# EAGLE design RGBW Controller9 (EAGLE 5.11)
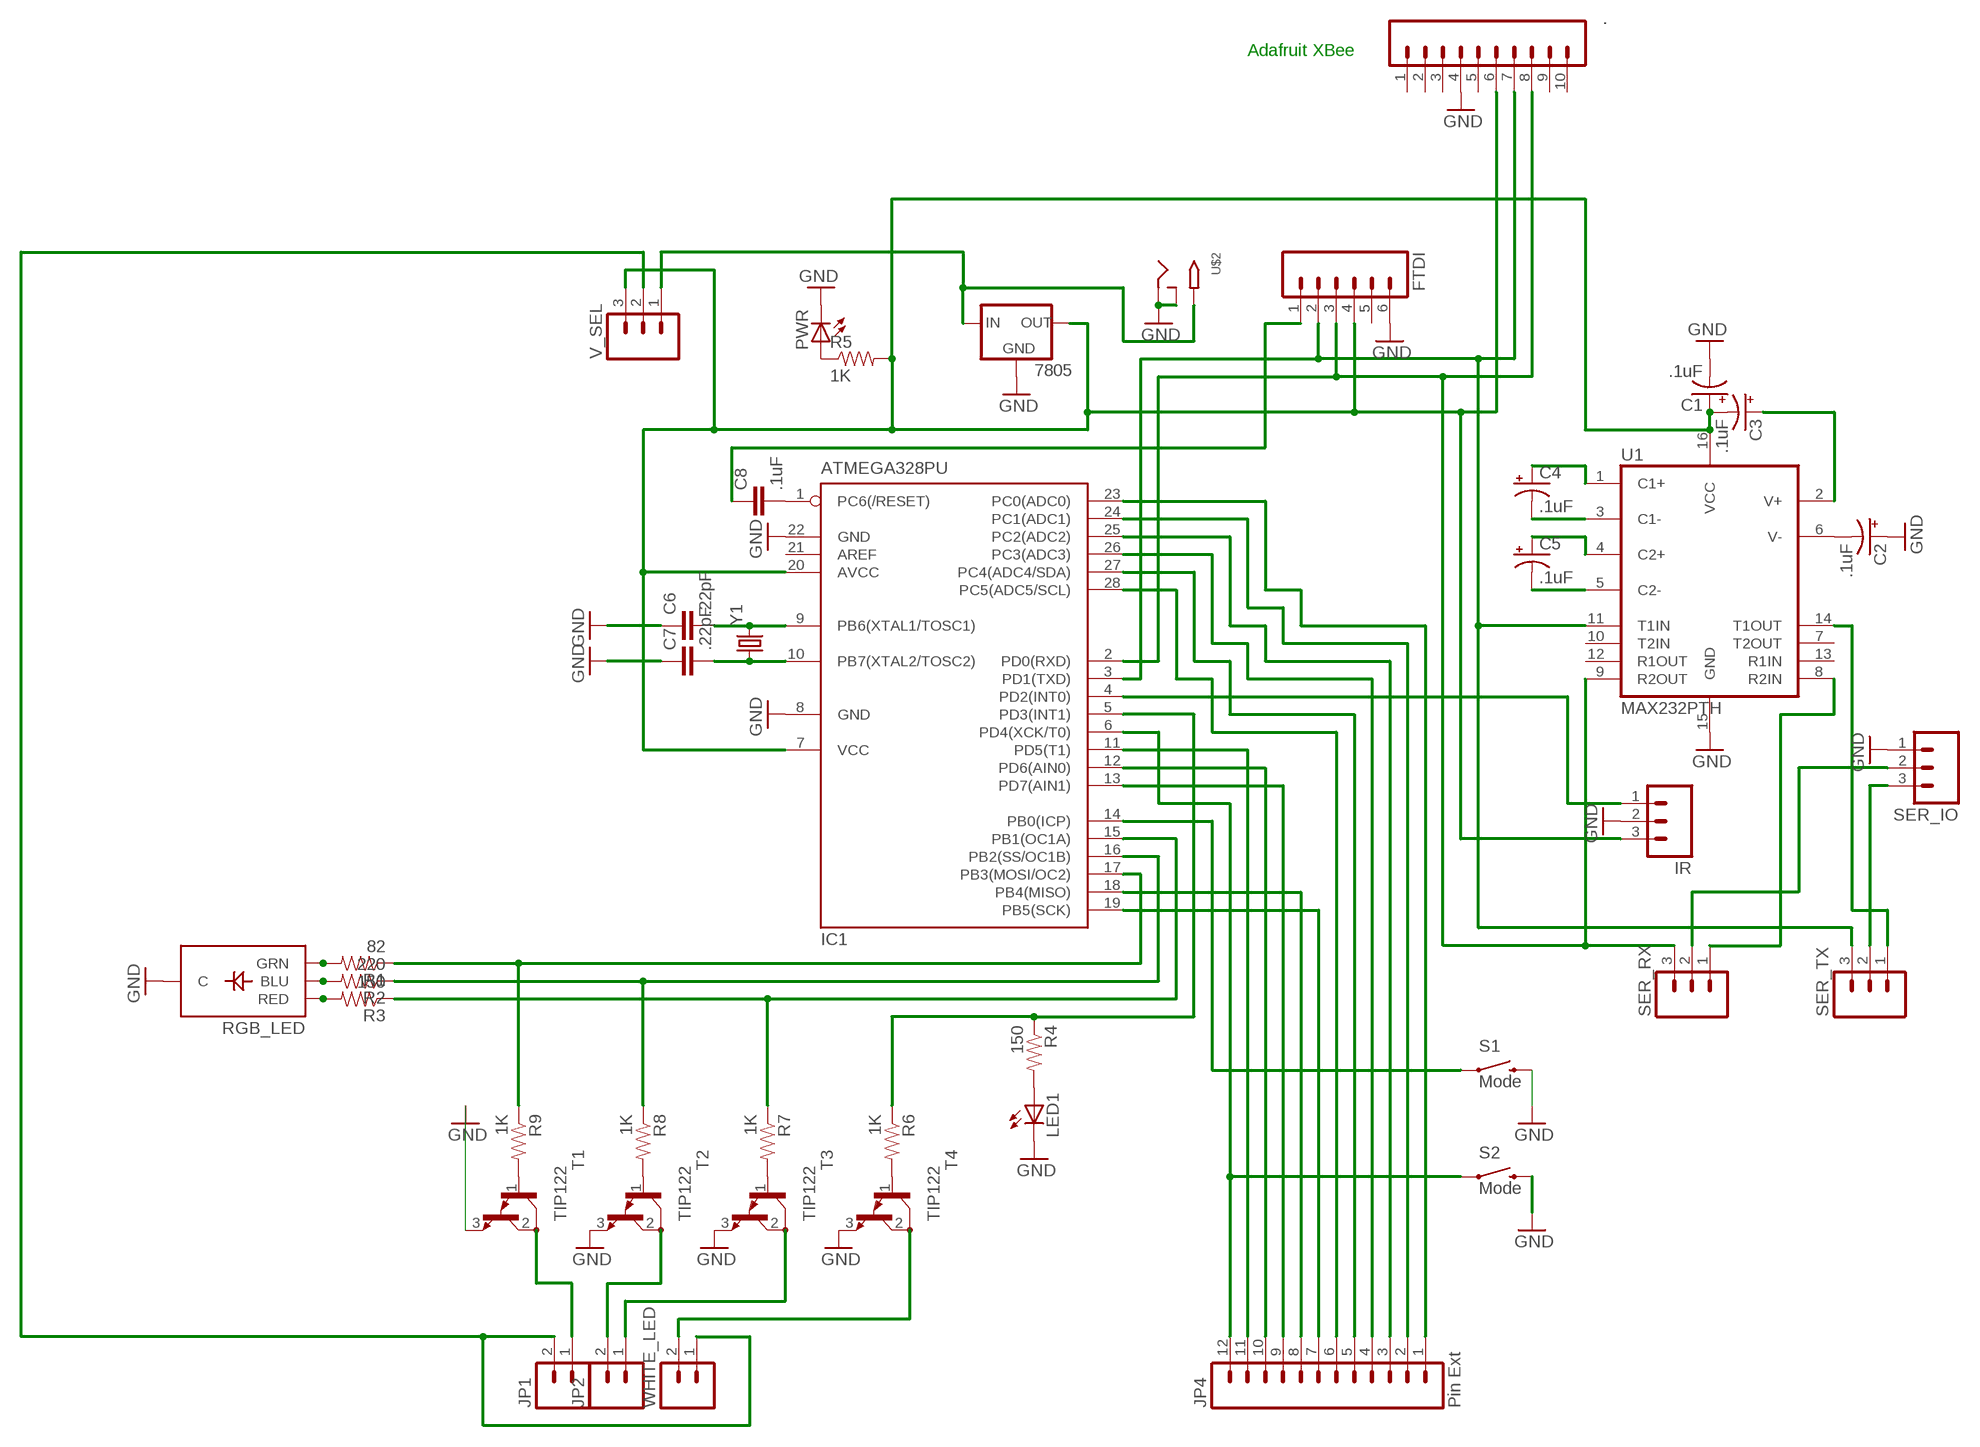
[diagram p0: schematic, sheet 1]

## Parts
7805  V_REG_78XXSIDE  [78XXL]
.  M10"  [1X10]
C1  .1uF  CAP_POLPTH1  [CPOL-RADIAL-100UF-25V]
C2  .1uF  CAP_POLPTH1  [CPOL-RADIAL-100UF-25V]
C3  .1uF  CAP_POLPTH1  [CPOL-RADIAL-100UF-25V]
C4  .1uF  CAP_POLPTH1  [CPOL-RADIAL-100UF-25V]
C5  .1uF  CAP_POLPTH1  [CPOL-RADIAL-100UF-25V]
C6  .22pF  CAPPTH  [CAP-PTH-SMALL]
C7  .22pF  CAPPTH  [CAP-PTH-SMALL]
C8  .1uF  CAPKIT  [CAP-PTH-SMALL-KIT]
FTDI  M06SIP  [1X06]
IC1  ATMEGA328PU  MEGA8-P  [DIL28-3]
IR  M03PTH  [1X03]
JP1  M023.5MM_LOCK  [SCREWTERMINAL-3.5MM-2_LOCK]
JP2  M023.5MM_LOCK  [SCREWTERMINAL-3.5MM-2_LOCK]
JP4  Pin Ext  M12LONGPADS  [1X12_LONGPADS]
LED1  LED5MM  [LED5MM]
PWR  LED5MM  [LED5MM]
R1  82  RESISTORPTH-1/4W  [AXIAL-0.4]
R2  220  RESISTORPTH-1/4W  [AXIAL-0.4]
R3  150  RESISTORPTH-1/4W  [AXIAL-0.4]
R4  150  RESISTORPTH-1/4W  [AXIAL-0.4]
R5  1K  RESISTORPTH-1/4W  [AXIAL-0.4]
R6  1K  RESISTORPTH-1/4W  [AXIAL-0.4]
R7  1K  RESISTORPTH-1/4W  [AXIAL-0.4]
R8  1K  RESISTORPTH-1/4W  [AXIAL-0.4]
R9  1K  RESISTORPTH-1/4W  [AXIAL-0.4]
RGB_LED  LED-TRICOLOR-THROUGHHOLE  [LED-TRICOLOR-THROUGHHOLE]
S1  Mode  SWITCH-MOMENTARY-2PTH  [TACTILE-PTH]
S2  Mode  SWITCH-MOMENTARY-2PTH  [TACTILE-PTH]
SER_IO  M03-SCREW-5MM  [SCREWTERMINAL-5MM-3]
SER_RX  M03PTH  [1X03]
SER_TX  M03PTH  [1X03]
T1  TIP122  [TO220]
T2  TIP122  [TO220]
T3  TIP122  [TO220]
T4  TIP122  [TO220]
U1  MAX232PTH  [DIL16]
U$2  2.1MMJACKTHM  [PJ-102A]
V_SEL  M03PTH  [1X03]
WHITE_LED  M023.5MM_LOCK  [SCREWTERMINAL-3.5MM-2_LOCK]
Y1  CRYSTALHC49US  [HC49US]

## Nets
GND: 7805.GND ..4 C1.2(-) C2.1(+) C6.1 C7.1 FTDI.6 IC1.8(GND) IC1.22(GND) IR.2 LED1.K(C) PWR.K(C) RGB_LED.GND(C) S1.3 S2.3 SER_IO.1 T1.3(E) T2.3(E) T3.3(E) T4.3(E) U1.15(GND) U$2.RING U$2.RING_SW
N$1: R1.P$2 RGB_LED.GRN
N$2: R2.P$2 RGB_LED.BLU
N$3: R3.P$2 RGB_LED.RED
N$4: LED1.A R4.P$2
N$5: PWR.A R5.P$1
N$6: C5.1(+) U1.4(C2+)
N$7: C4.2(-) U1.3(C1-)
N$8: C4.1(+) U1.1(C1+)
N$9: C5.2(-) U1.5(C2-)
N$10: IC1.19(PB5(SCK)) JP4.7
N$11: C3.1(+) U1.2(V+)
N$12: C2.2(-) U1.6(V-)
N$13: IC1.5(PD3(INT1)) R4.P$1 R6.P$1
N$14: IC1.15(PB1(OC1A)) R3.P$1 R7.P$1
N$15: IC1.16(PB2(SS/OC1B)) R2.P$1 R8.P$1
N$16: IC1.17(PB3(MOSI/OC2)) R1.P$1 R9.P$1
N$17: C6.2 IC1.9(PB6(XTAL1/TOSC1)) Y1.2
N$18: C7.2 IC1.10(PB7(XTAL2/TOSC2)) Y1.1
N$19: IC1.4(PD2(INT0)) IR.1
N$20: JP1.2 V_SEL.2 WHITE_LED.1
N$21: JP1.1 T1.2(C)
N$22: 7805.OUT ..6 C1.1(+) C3.2(-) FTDI.4 IC1.7(VCC) IC1.20(AVCC) IR.3 R5.P$2 U1.16(VCC) V_SEL.3
N$23: JP2.2 T2.2(C)
N$24: JP2.1 T3.2(C)
N$25: T4.2(C) WHITE_LED.2
N$26: IC1.14(PB0(ICP)) S1.1
N$27: C8.2 IC1.1(PC6(/RESET))
N$28: C8.1 FTDI.1
N$29: ..7 FTDI.2 IC1.3(PD1(TXD)) SER_TX.3 U1.11(T1IN)
N$30: ..8 FTDI.3 IC1.2(PD0(RXD)) SER_RX.3 U1.9(R2OUT)
N$31: IC1.18(PB4(MISO)) JP4.8
N$32: IC1.13(PD7(AIN1)) JP4.9
N$33: IC1.12(PD6(AIN0)) JP4.10
N$34: IC1.11(PD5(T1)) JP4.11
N$35: IC1.26(PC3(ADC3)) JP4.4
N$36: IC1.27(PC4(ADC4/SDA)) JP4.5
N$37: IC1.28(PC5(ADC5/SCL)) JP4.6
N$38: IC1.6(PD4(XCK/T0)) JP4.12 S2.1
N$39: IC1.25(PC2(ADC2)) JP4.3
N$40: IC1.24(PC1(ADC1)) JP4.2
N$41: IC1.23(PC0(ADC0)) JP4.1
N$42: SER_IO.3 SER_TX.2
N$43: SER_IO.2 SER_RX.2
N$44: SER_TX.1 U1.14(T1OUT)
N$45: SER_RX.1 U1.8(R2IN)
N$46: R7.P$2 T3.1(B)
N$47: R8.P$2 T2.1(B)
N$48: R9.P$2 T1.1(B)
N$49: R6.P$2 T4.1(B)
N$50: 7805.IN U$2.TIP V_SEL.1
Unconnected: ..1 ..2 ..3 ..5 ..9 ..10 FTDI.5 IC1.21(AREF) U1.7(T2OUT) U1.10(T2IN) U1.12(R1OUT) U1.13(R1IN)

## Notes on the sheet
- Adafruit XBee

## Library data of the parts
7805 = SparkFun:V_REG_78XX: Voltage Regulator Standard 7805 5V regulator. IGO (Input Ground Output). Spark Fun Electronics SKU : COM-00107
. = SparkFun:M10: Header 10 Standard 10-pin 0.1" header. Use with straight break away headers (SKU : PRT-00116), right angle break away headers (PRT-00553), swiss pins (PRT-00743), machine pins (PRT-00117), and female headers (PRT-00115).
C1-C5 = SparkFun:CAP_POL: Capacitor Polarized
C6-C8 = SparkFun:CAP: Capacitor
FTDI = SparkFun:M06: Header 6 Standard 6-pin 0.1" header. Use with straight break away headers (SKU : PRT-00116), right angle break away headers (PRT-00553), swiss pins (PRT-00743), machine pins (PRT-00117), and female headers (PRT-00115). Molex polarized connector foot print use with SKU : PRT-08094 with associated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
IC1 = atmel:MEGA8-P: MICROCONTROLLER 8 Kbytes FLASH, 1 kbytes SRAM, 512 bytes EEPROM, USART, 4-channel 10 bit ADC, 2-channel 8 bit ADC Pin compatible with Atmega48, ATMega88, ATMega168 Source: avr.lbr
IR SER_IO SER_RX SER_TX V_SEL = SparkFun:M03: Header 3 Standard 3-pin 0.1" header. Use with straight break away headers (SKU : PRT-00116), right angle break away headers (PRT-00553), swiss pins (PRT-00743), machine pins (PRT-00117), and female headers (PRT-00115). Molex polarized connector foot print use with SKU : PRT-08232 with associated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
JP1 JP2 WHITE_LED = SparkFun:M02: Header 2
JP4 = SparkFun:M12: Header 12 Standard 12-pin 0.1" header. Use with straight break away headers (SKU : PRT-00116), right angle break away headers (PRT-00553), swiss pins (PRT-00743), machine pins (PRT-00117), and female headers (PRT-00115).
LED1 PWR = led:LED: LED
R1-R9 = SparkFun:RESISTOR: Resistor
RGB_LED = SparkFun:LED-TRICOLOR-THROUGHHOLE
S1 S2 = SparkFun:SWITCH-MOMENTARY-2
T1-T4 = transistor:TIP122: NPN BIPOLAR DARLINGTON TRANSISTOR
U1 = SparkFun:MAX232: RS232 Transceiver Very common IC. This is generically called 'MAX232', but works with the 3V equivalent MAX3232 generic ICs. Field tested and mother approved. Spark Fun Electronics SKU : COM-00316 (DIP) and COM-00589 (SMD)
U$2 = adafruit:2.1MMJACK: 2.1mm x 5.5mm THM DC jack with internal switch. Digikey part #PJ-102A, 4UCON part #05537 2.1mm x 5.5mm SMT DC jack with internal switch. Digikey part #PJ-002A-SMT, 4UCON part #03267 By microbuilder.eu & adafruit.com
Y1 = SparkFun:CRYSTAL: Crystals

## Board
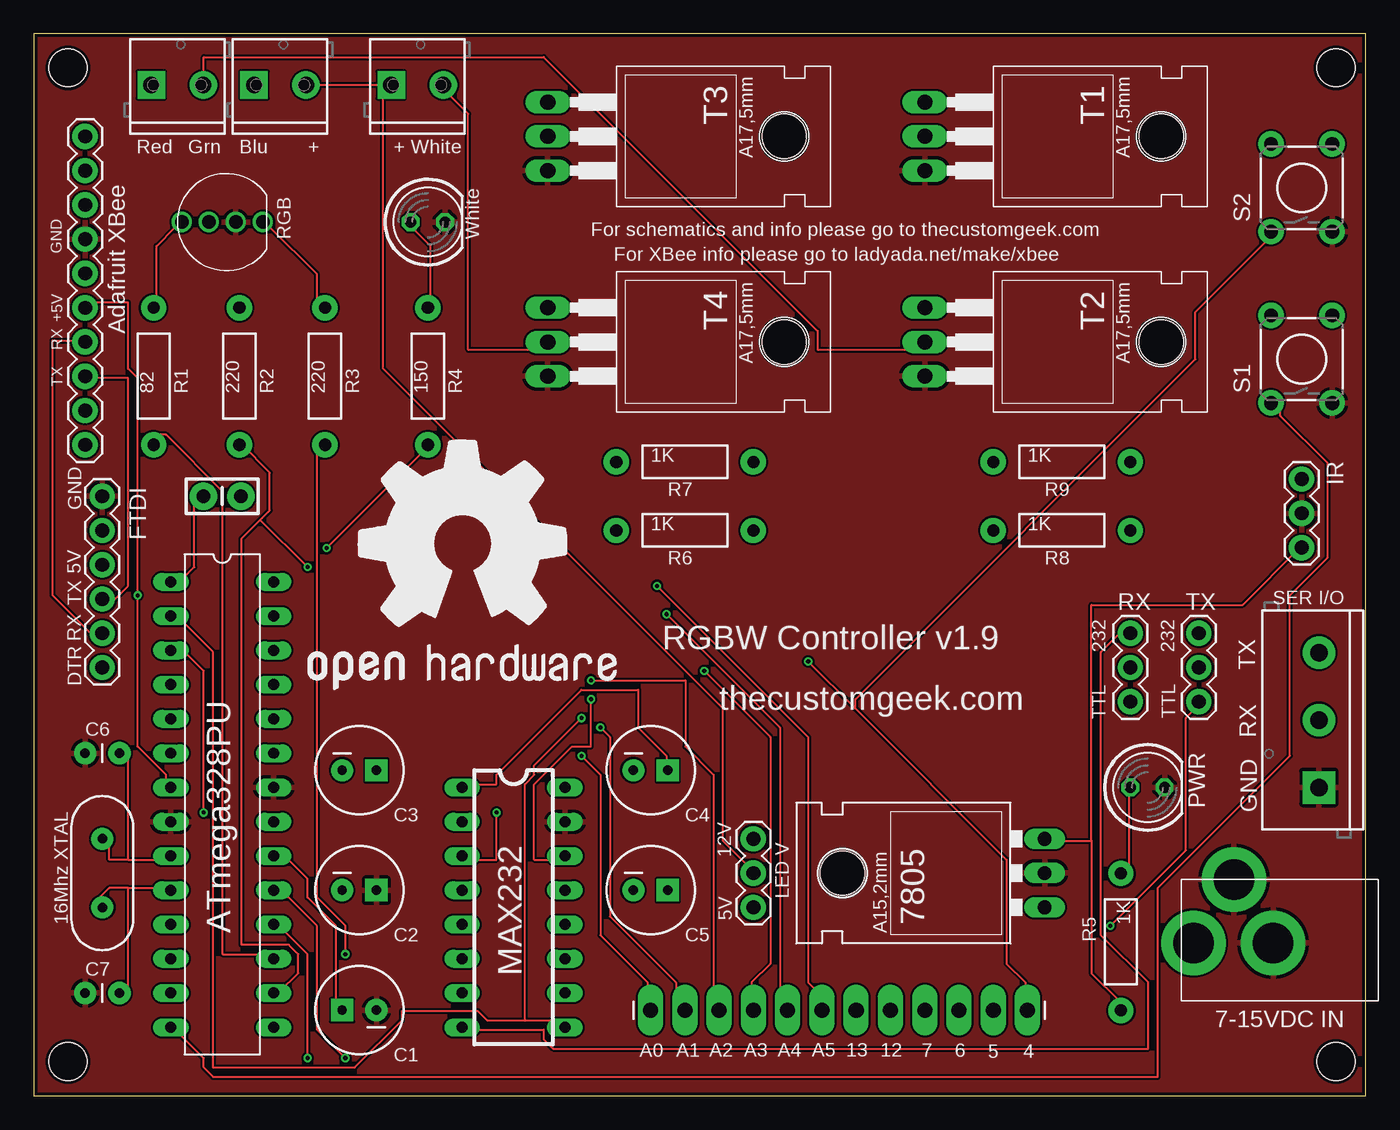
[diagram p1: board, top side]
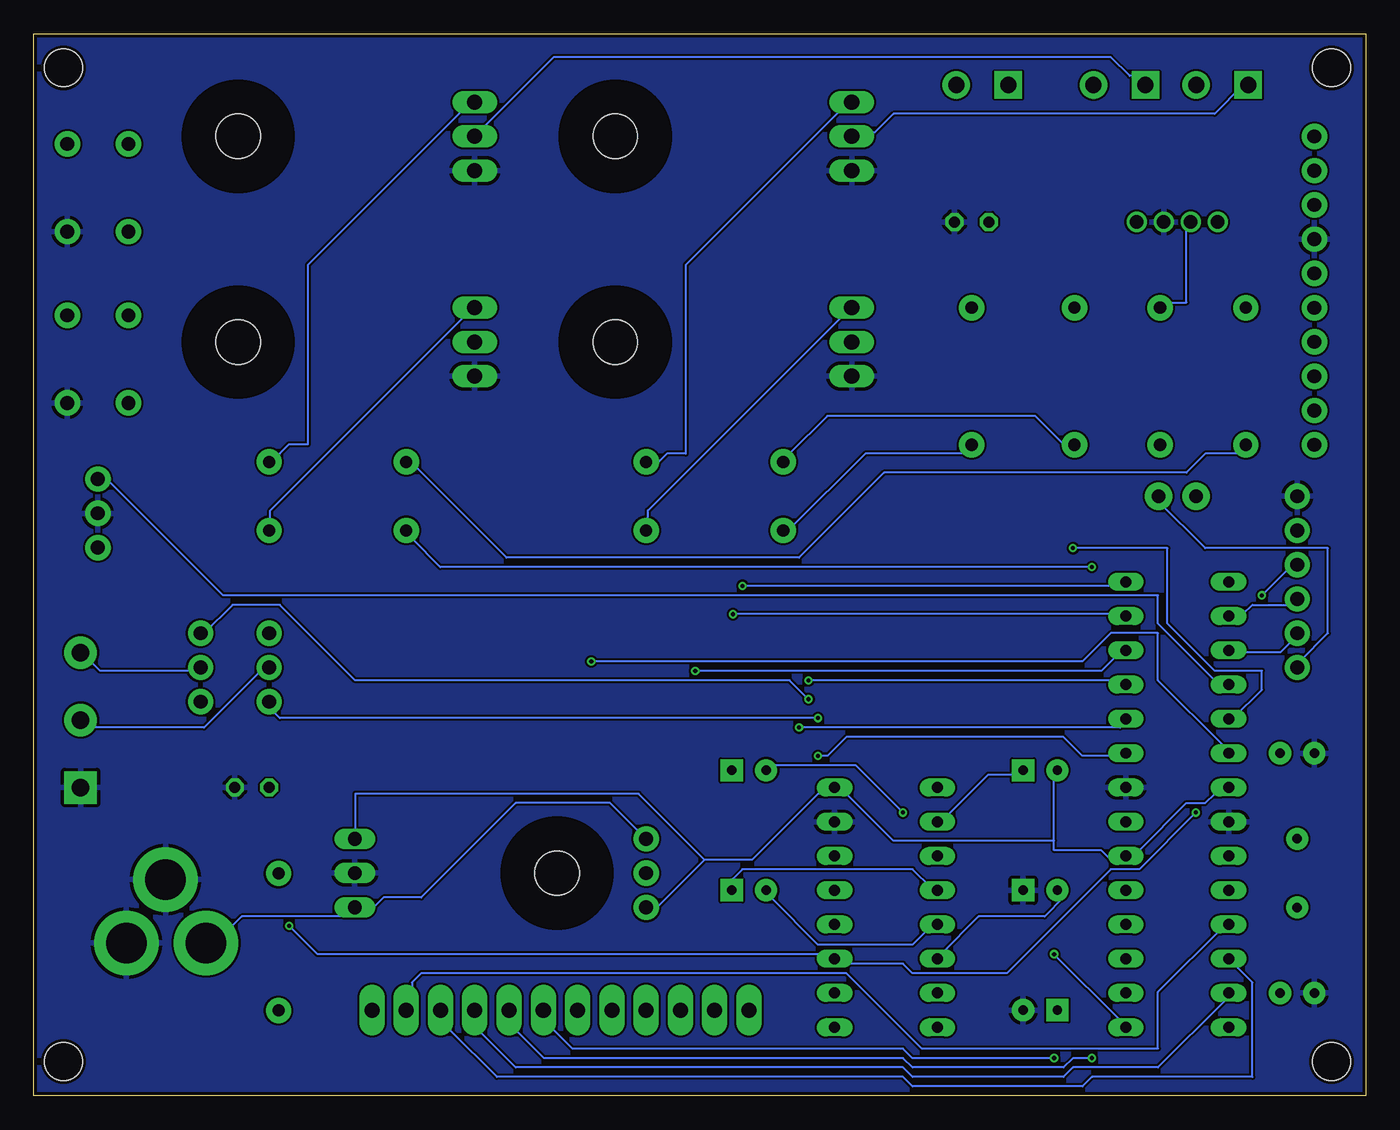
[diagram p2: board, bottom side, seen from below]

Size 98.73 x 78.73 mm. Coordinates in mm from the lower left corner, seen from the top.
Outline: 0,0 98.73,0 98.73,78.73 0,78.73 0,0
Copper layers (1*16): Top 0.035mm / dielectric 1.5mm / Bottom 0.035mm
Design rules "Fusion_eagle_rule_v1.1": minimum track width 6mil, minimum drill 12mil, track to track 6mil, track to pad 6mil, pad to pad 6mil, via to via 6mil, smd to smd 0mil, copper to edge 10mil, drill to drill 10mil, minimum pad ring 10mil, minimum via ring 6mil, stop-mask expansion 2mil, vias tented up to drill 100mil, thermal gap 10mil
Holes 2.8 mm at 2.54,76.2 2.54,2.54 96.52,2.54 96.52,76.2

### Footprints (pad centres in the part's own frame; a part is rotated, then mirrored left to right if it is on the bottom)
78XXL = drill 1.016 long: GND 0,-3.81; IN -2.54,-3.81; OUT 2.54,-3.81 | hole 3.302: 0,11.176
1X10 = drill 1.016 pad 1.88 round: 1 0,0; 2 2.54,0; 3 5.08,0; 4 7.62,0; 5 10.16,0; 6 12.7,0; 7 15.24,0; 8 17.78,0; 9 20.32,0; 10 22.86,0
CPOL-RADIAL-100UF-25V = drill 0.7 pad 1.651 square: 1 1.27,0 | drill 0.7 pad 1.651 round: 2 -1.27,0
CAP-PTH-SMALL = drill 0.7 pad 1.651 round: 1 0,0; 2 2.54,0
CAP-PTH-SMALL-KIT = drill 1.016 pad 2.032 round: 1 -1.397,0; 2 1.397,0
1X06 = drill 1.016 pad 1.88 round: 1 0,0; 2 2.54,0; 3 5.08,0; 4 7.62,0; 5 10.16,0; 6 12.7,0
DIL28-3 = drill 0.813 long: 1 -16.51,-3.81; 2 -13.97,-3.81; 3 -11.43,-3.81; 4 -8.89,-3.81; 5 -6.35,-3.81; 6 -3.81,-3.81; 7 -1.27,-3.81; 8 1.27,-3.81; 9 3.81,-3.81; 10 6.35,-3.81; 11 8.89,-3.81; 12 11.43,-3.81; 13 13.97,-3.81; 14 16.51,-3.81; 15 16.51,3.81; 16 13.97,3.81; 17 11.43,3.81; 18 8.89,3.81; 19 6.35,3.81; 20 3.81,3.81; 21 1.27,3.81; 22 -1.27,3.81; 23 -3.81,3.81; 24 -6.35,3.81; 25 -8.89,3.81; 26 -11.43,3.81; 27 -13.97,3.81; 28 -16.51,3.81
1X03 = drill 1.016 pad 1.88 round: 1 0,0; 2 2.54,0; 3 5.08,0
SCREWTERMINAL-3.5MM-2_LOCK = drill 1.2 pad 2.032 square: 1 -0.178,0 | drill 1.2 pad 2.032 round: 2 3.678,0
1X12_LONGPADS = drill 1.118 pad 1.88 long: 1 0,0; 2 2.54,0; 3 5.08,0; 4 7.62,0; 5 10.16,0; 6 12.7,0; 7 15.24,0; 8 17.78,0; 9 20.32,0; 10 22.86,0; 11 25.4,0; 12 27.94,0
LED5MM = drill 0.813 octagon: A -1.27,0; K 1.27,0
AXIAL-0.4 = drill 0.9 pad 1.88 round: P$1 -5.08,0; P$2 5.08,0
LED-TRICOLOR-THROUGHHOLE = drill 1 round: BLU 1,0; GND -1,0; GRN 3,0; RED -3,0
TACTILE-PTH = drill 1.016 pad 1.88 round: 1 -3.251,2.261; 2 3.251,2.261; 3 -3.251,-2.261; 4 3.251,-2.261
SCREWTERMINAL-5MM-3 = drill 1.3 pad 2.413 square: 1 0,0 | drill 1.3 pad 2.413 round: 2 5,0; 3 10,0
TO220 = drill 1.118 long: 1 -2.54,-6.35; 2 0,-6.35; 3 2.54,-6.35 | hole 3.302: 0,11.176
DIL16 = drill 0.813 long: 1 -8.89,-3.81; 2 -6.35,-3.81; 3 -3.81,-3.81; 4 -1.27,-3.81; 5 1.27,-3.81; 6 3.81,-3.81; 7 6.35,-3.81; 8 8.89,-3.81; 9 8.89,3.81; 10 6.35,3.81; 11 3.81,3.81; 12 1.27,3.81; 13 -1.27,3.81; 14 -3.81,3.81; 15 -6.35,3.81; 16 -8.89,3.81
PJ-102A = drill 3 pad 4.8 round: RING 0.1,-3.39; RING_SW -4.6,-6.29; TIP 0.1,-9.29
HC49US = drill 0.7 pad 1.651 round: 1 -2.54,0; 2 2.54,0

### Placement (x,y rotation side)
7805  71.12,16.51 90 top
.  3.81,71.12 270 top
C1  24.13,6.35 180 top
C2  24.13,15.24 0 top
C3  24.13,24.13 0 top
C4  45.72,24.13 0 top
C5  45.72,15.24 0 top
C6  3.81,25.4 0 top
C7  3.81,7.62 0 top
C8  13.97,44.45 180 top
FTDI  5.08,31.75 90 top
IC1  13.97,21.59 270 top
IR  93.98,45.72 270 top
JP1  16.51,74.93 0 top
JP2  8.89,74.93 0 top
JP4  45.72,6.35 0 top
LED1  29.21,64.77 0 top
PWR  82.55,22.86 0 top
R1  8.89,53.34 90 top
R2  15.24,53.34 90 top
R3  21.59,53.34 90 top
R4  29.21,53.34 90 top
R5  80.58,11.41 270 top
R6  48.26,41.91 0 top
R7  48.26,46.99 0 top
R8  76.2,41.91 0 top
R9  76.2,46.99 0 top
RGB_LED  13.97,64.77 180 top
S1  93.98,54.61 90 top
S2  93.98,67.31 90 top
SER_IO  95.25,22.86 90 top
SER_RX  81.28,34.29 270 top
SER_TX  86.36,34.29 270 top
T1  72.39,71.12 270 top
T2  72.39,55.88 270 top
T3  44.45,71.12 270 top
T4  44.45,55.88 270 top
U1  35.56,13.97 270 top
U$1  [OSHW0]  19.05,26.67 0 top
U$2  95.25,11.43 270 top
V_SEL  53.34,19.05 270 top
WHITE_LED  26.67,74.93 0 top
Y1  5.08,16.51 90 top

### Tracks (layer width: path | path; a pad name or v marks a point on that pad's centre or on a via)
GND
  pour Bottom: 0,78.74 99.06,78.74 99.06,0 0,0
  pour Top: 0,78.74 99.06,78.74 99.06,0 0,0
N$1
  Top 0.152: RGB_LED.GRN 10.5,64.4 9.1,63 9.1,58.8 R1.P$2
N$2
  Bottom 0.152: RGB_LED.BLU 13.3,64.4 13.3,58.8 14.7,58.8 R2.P$2
N$3
  Top 0.152: RGB_LED.RED 17.5,64.4 21,60.9 21,58.8 R3.P$2
N$4
  Top 0.152: LED1.A 28,64.4 29.4,63 29.4,58.8 R4.P$2
N$5
  Top 0.152: PWR.A 81.2,22.4 81.2,16.8 R5.P$1
N$6
  Bottom 0.152: U1.4 32.2,15.4 33.6,16.8 46.2,16.8 47.6,15.4 C5.1
N$7  (via drill 0.3)
  Top 0.152: v34.3,21 34.3,17.5 32.2,17.5 U1.3
  Bottom 0.152: v34.3,21 37.8,24.5 44.1,24.5 C4.2
N$8
  Top 0.152: U1.1 32.2,23.1 34.3,23.1 34.3,23.8 40.6,30.1 44.8,30.1 44.8,27.3 46.9,25.2 46.9,24.5 C4.1
N$9
  Bottom 0.152: U1.5 32.2,12.6 33.6,11.2 40.6,11.2 44.1,14.7 C5.2
N$10  (via drill 0.3)
  Top 0.152: v23.1,2.8 21,4.9 21,12.6 18.9,14.7 18.2,14.7 IC1.19
  Bottom 0.152: v23.1,2.8 33.6,2.8 34.3,3.5 58.8,3.5 61.6,6.3 JP4.7
N$11
  Bottom 0.152: U1.2 31.5,20.3 28,23.8 25.9,23.8 C3.1
N$12
  Bottom 0.152: U1.6 31.5,10.5 28.7,13.3 23.8,13.3 22.4,14.7 C2.2
N$13  (via drill 0.3)
  Top 0.152: v21.7,40.6 28.7,47.6 R4.P$1
  Bottom 0.152: v21.7,40.6 14.7,40.6 14.7,35 11.2,31.5 7.7,31.5 7.7,30.1 9.8,28 IC1.5 | R6.P$1 42.7,42 37.1,47.6 29.4,47.6 R4.P$1
N$14  (via drill 0.3)
  Top 0.152: v23.1,10.5 23.1,12.6 21,14.7 21,47.6 R3.P$1
  Bottom 0.152: v23.1,10.5 18.2,5.6 IC1.15 | R7.P$1 42.7,47.6 39.9,50.4 24.5,50.4 22.4,48.3 21.7,48.3 R3.P$1
N$15  (via drill 0.3)
  Top 0.152: 16.8,42.7 17.5,43.4 17.5,46.2 15.4,48.3 R2.P$1 | 16.8,42.7 15.4,41.3 15.4,11.2 18.9,11.2 19.6,10.5 19.6,9.1 18.2,7.7 IC1.16 | 16.8,42.7 v20.3,39.2
  Bottom 0.152: v20.3,39.2 68.6,39.2 70.7,41.3 R8.P$1
N$16
  Top 0.152: IC1.17 17.5,10.5 14,10.5 14,44.8 9.8,49 9.1,49 9.1,48.3 R1.P$1
  Bottom 0.152: R9.P$1 70.7,46.9 63.7,39.9 42,39.9 35.7,46.2 13.3,46.2 11.9,47.6 9.1,47.6 R1.P$1
N$17
  Top 0.152: 7,17.5 5.6,17.5 5.6,18.9 Y1.2 | 7,17.5 9.8,17.5 IC1.9 | 7,17.5 7,25.2 C6.2
N$18
  Top 0.152: 7,15.4 5.6,15.4 4.9,14.7 4.9,14 Y1.1 | 7,15.4 9.8,15.4 IC1.10 | 7,15.4 7,7.7 C7.2
N$19
  Bottom 0.152: IC1.4 10.5,30.8 11.2,30.8 15.4,35 15.4,37.1 84.7,37.1 93.1,45.5 93.8,45.5 IR.1
N$20
  Top 0.152: 25.9,74.9 25.9,53.9 51.1,28.7 51.1,18.9 53.2,16.8 V_SEL.2 | 25.9,74.9 20.3,74.9 JP1.2 | 25.9,74.9 WHITE_LED.1
N$21
  Bottom 0.152: T1.2 65.8,71.4 60.2,77 18.9,77 17.5,75.6 16.8,75.6 JP1.1
N$22  (via drill 0.3)
  Top 0.152: 78.4,18.9 75.6,18.9 7805.OUT | 78.4,18.9 78.4,9.1 80.5,7 R5.P$2 | 78.4,18.9 78.4,36.4 89.6,36.4 93.8,40.6 IR.3 | C1.1 22.4,7 22.4,12.6 20.3,14.7 20.3,16.1 18.2,18.2 IC1.20 | IC1.7 9.8,23.1 9.8,23.8 7.7,25.9 v7.7,37.1 7.7,53.2 7,53.9 7,58.8 4.2,58.8 ..6
  Bottom 0.152: 49,17.5 45.5,17.5 40.6,22.4 39.9,22.4 U1.16 39.2,22.4 38.5,22.4 35,18.9 23.1,18.9 | 49,17.5 52.5,14 53.2,14 V_SEL.3 | IC1.7 10.5,22.4 11.2,22.4 11.9,21.7 13.3,21.7 16.8,18.2 17.5,18.2 IC1.20 18.2,17.5 18.9,17.5 19.6,18.2 23.1,18.2 23.1,18.9 | 23.1,18.9 23.1,23.8 C3.2 | v7.7,37.1 5.6,39.2 FTDI.4 | 49,17.5 53.9,22.4 74.9,22.4 74.9,19.6 7805.OUT
N$23
  Top 0.152: T2.2 65.8,55.3 58.1,55.3 58.1,56.7 37.8,77 12.6,77 12.6,75.6 JP2.2
N$24
  Bottom 0.152: T3.2 37.8,71.4 36.4,71.4 35,72.8 11.2,72.8 9.1,74.9 JP2.1
N$25
  Top 0.152: T4.2 37.8,55.3 32.2,55.3 32.2,72.8 30.8,74.2 30.8,74.9 WHITE_LED.2
N$26
  Top 0.152: IC1.14 10.5,4.9 12.6,2.8 12.6,2.1 13.3,1.4 83.3,1.4 83.3,15.4 93.1,25.2 93.1,37.1 95.9,39.9 95.9,46.9 92.4,50.4 92.4,51.1 S1.1
N$27
  Top 0.152: IC1.1 10.5,38.5 11.2,38.5 11.9,39.2 11.9,44.1 C8.2
N$28
  Bottom 0.152: FTDI.1 4.9,32.2 2.8,34.3 2.8,40.6 11.9,40.6 15.4,44.1 C8.1
N$29  (via drill 0.3)
  Top 0.152: v12.6,21 12.6,31.5 10.5,33.6 IC1.3 | ..7 3.5,56 1.4,56 1.4,37.1 4.9,33.6 FTDI.2 | v79.8,12.6 85.4,18.2 85.4,28 86.1,28.7 SER_TX.3
  Bottom 0.152: IC1.3 9.8,32.9 6.3,32.9 5.6,33.6 FTDI.2 | v12.6,21 16.8,16.8 18.9,16.8 26.6,9.1 33.6,9.1 34.3,9.8 39.2,9.8 U1.11 39.9,10.5 77.7,10.5 v79.8,12.6
N$30  (via drill 0.3)
  Top 0.152: 36.4,5.6 33.6,5.6 32.9,6.3 27.3,6.3 27.3,5.6 23.8,2.1 13.3,2.1 13.3,32.9 10.5,35.7 IC1.2 | 36.4,5.6 39.2,5.6 U1.9 | ..8 4.2,53.2 7,53.2 7,37.8 5.6,36.4 FTDI.3 | v40.6,28 37.1,24.5 37.1,23.8 36.4,23.1 36.4,5.6
  Bottom 0.152: FTDI.3 5.6,36.4 8.4,36.4 9.1,35.7 9.8,35.7 IC1.2 | v40.6,28 80.5,28 81.2,28.7 SER_RX.3
N$31  (via drill 0.3)
  Top 0.152: v20.3,2.8 20.3,10.5 18.2,12.6 IC1.18
  Bottom 0.152: v20.3,2.8 21.7,2.8 22.4,2.1 33.6,2.1 34.3,2.8 60.9,2.8 63,4.9 63,6.3 JP4.8
N$32
  Bottom 0.152: IC1.13 10.5,7 15.4,2.1 21.7,2.1 22.4,1.4 33.6,1.4 34.3,2.1 63,2.1 65.8,4.9 65.8,6.3 JP4.9
N$33
  Bottom 0.152: IC1.12 8.4,8.4 8.4,1.4 20.3,1.4 21,0.7 33.6,0.7 34.3,1.4 64.4,1.4 67.9,4.9 67.9,6.3 JP4.10
N$34
  Bottom 0.152: IC1.11 10.5,12.6 15.4,7.7 15.4,3.5 32.9,3.5 38.5,9.1 70,9.1 70.7,8.4 70.7,7 JP4.11
N$35  (via drill 0.3)
  Top 0.152: v49.7,31.5 54.6,26.6 54.6,9.8 53.2,8.4 53.2,7 JP4.4
  Bottom 0.152: v49.7,31.5 19.6,31.5 18.2,32.9 IC1.26
N$36  (via drill 0.3)
  Top 0.152: v46.9,35.7 55.3,27.3 55.3,7 JP4.5
  Bottom 0.152: v46.9,35.7 18.2,35.7 IC1.27
N$37  (via drill 0.3)
  Top 0.152: v46.2,37.8 57.4,26.6 57.4,8.4 58.1,7.7 58.1,7 JP4.6
  Bottom 0.152: v46.2,37.8 18.2,37.8 IC1.28
N$38  (via drill 0.3)
  Top 0.152: 60.9,28.7 72.1,17.5 72.1,9.8 73.5,8.4 73.5,7 JP4.12 | v57.4,32.2 60.9,28.7 | 60.9,28.7 60.9,29.4 86.1,54.6 86.1,58.1 91.7,63.7 S2.1 | 60.9,28.7
  Bottom 0.152: v57.4,32.2 21,32.2 18.9,34.3 15.4,34.3 15.4,30.8 10.5,25.9 IC1.6
N$39  (via drill 0.3)
  Top 0.152: v41.3,30.8 48.3,30.8 48.3,25.9 50.4,23.8 50.4,7 JP4.3
  Bottom 0.152: v41.3,30.8 18.2,30.8 IC1.25
N$40  (via drill 0.3)
  Top 0.152: v42,27.3 42.7,26.6 42.7,13.3 47.6,8.4 47.6,7 JP4.2
  Bottom 0.152: v42,27.3 18.2,27.3 IC1.24
N$41  (via drill 0.3)
  Top 0.152: v40.6,25.2 42,23.8 42,11.9 45.5,8.4 45.5,7 JP4.1
  Bottom 0.152: v40.6,25.2 39.9,25.2 38.5,26.6 22.4,26.6 21,25.2 18.2,25.2 IC1.23
N$42
  Bottom 0.152: SER_TX.2 86.8,31.5 93.8,31.5 94.5,32.2 95.2,32.2 SER_IO.3
N$43
  Bottom 0.152: SER_RX.2 81.9,31.5 86.1,27.3 95.2,27.3 SER_IO.2
N$44  (via drill 0.3)
  Top 0.152: v41.3,29.4 41.3,25.9 39.9,25.9 37.1,23.1 37.1,17.5 39.2,17.5 U1.14
  Bottom 0.152: v41.3,29.4 42.7,30.8 74.9,30.8 80.5,36.4 84,36.4 86.1,34.3 SER_TX.1
N$45
  Top 0.152: U1.8 32.2,4.9 37.8,4.9 37.8,4.2 38.5,3.5 82.6,3.5 82.6,8.4 79.1,11.9 79.1,32.9 80.5,34.3 81.2,34.3 SER_RX.1
N$46
  Bottom 0.152: T3.1 38.5,73.5 50.4,61.6 50.4,47.6 51.8,47.6 52.5,46.9 53.2,46.9 R7.P$2
N$47
  Bottom 0.152: T2.1 66.5,58.1 81.2,43.4 81.2,42 R8.P$2
N$48
  Bottom 0.152: T1.1 66.5,73.5 78.4,61.6 78.4,48.3 79.8,48.3 80.5,47.6 81.2,47.6 R9.P$2
N$49
  Bottom 0.152: T4.1 38.5,58.1 53.2,43.4 53.2,42 R6.P$2
N$50
  Bottom 0.152: U$2.TIP 85.4,11.9 84.7,11.9 83.3,13.3 75.6,13.3 7805.IN 74.9,14 73.5,14 72.8,14.7 70,14.7 63,21.7 56,21.7 53.9,19.6 V_SEL.1

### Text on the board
tPlace: Red | Grn | Blu | + | + | White | RGB | White | For schematics and info please go to thecustomgeek.com | GND | For XBee info please go to ladyada.net/make/xbee | +5V | Adafruit XBee | RX | TX | 82 | R1 | 220 | R2 | 220 | R3 | 150 | R4 | 1K | 1K | R7 | R9 | GND | 1K | 1K | 5V | R6 | R8 | TX | RX | TX | SER I/O | RX | RGBW Controller v1.9 | 232 | 232 | TX | DTR | thecustomgeek.com | TTL | TTL | C6 | RX | GND | C3 | C4 | LED V | 12V | 16Mhz XTAL | 5V | 1K | ATmega328PU | C2 | C5 | R5 | C7 | MAX232 | 7-15VDC IN | C1 | A0 | A1 | A2 | A3 | A4 | A5 | 13 | 12 | 7 | 6 | 5 | 4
